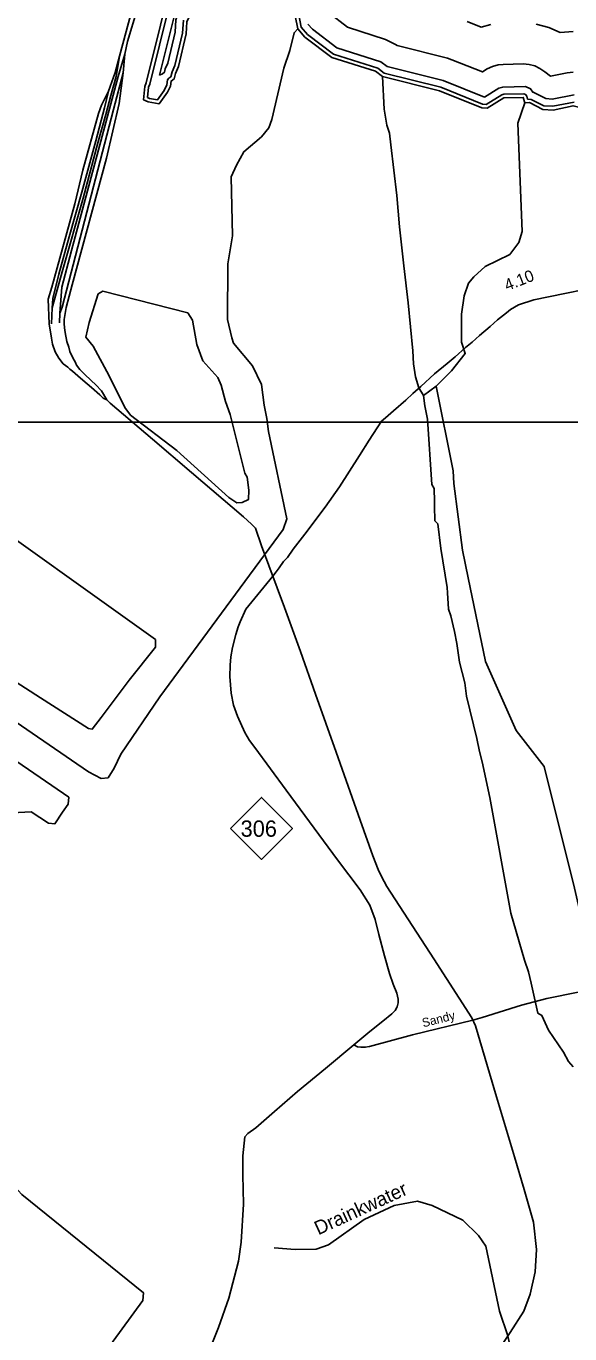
# Model space of a CAD drawing. Extents: x 2532689 to 2764727, y 536648 to 732970.
# Drawn here: x 2661812 to 2667660, y 588019 to 602075 of the extents above; entities that cross this region are included whole.
import ezdxf

# ---------------------------------------------------------------- set-up
doc = ezdxf.new("R2010")
doc.units = 0
for name, color, linetype in [('Exist Hydrographic Buffer Line', 7, 'Continuous'), ('Exist Hydrographic Creek Single Shore', 7, 'Continuous'), ('Exist Hydrographic Creek Single Shore Label', 7, 'Continuous'), ('Exist Hydrographic River Shore', 7, 'Continuous'), ('Exist Railroad Mainline', 7, 'Continuous'), ('Exist Railroad Siding', 7, 'Continuous'), ('Exist Road Primary NC Attributed', 7, 'Continuous'), ('Exist Road Primary NC Mileage Hundredths English Label', 7, 'Continuous'), ('Exist Road Primary NC Shield CELL', 7, 'Continuous'), ('Exist Road Primary NC Shield Number Label', 7, 'Continuous'), ('Exist Road Secondary Type 20 Attributed', 7, 'Continuous'), ('Exist Road Secondary Type 51 Attributed', 7, 'Continuous'), ('Exist Road Secondary Type 51 Label', 7, 'Continuous'), ('Map Preparation Inset Cut Line', 7, 'Continuous')]:
    doc.layers.add(name, color=color, linetype=linetype)

msp = doc.modelspace()

# ---------------------------------------------------------------- linework, layer by layer
at = {"layer": 'Exist Hydrographic Buffer Line'}
for points in [[(2663764, 603955), (2663142, 601452), (2663128, 601418), (2663118, 601309), (2663138, 601299), (2663225, 601283), (2663297, 601385), (2663325, 601443), (2663333, 601498), (2663347, 601516), (2663369, 601532), (2663383, 601584), (2663413, 601654), (2663495, 601999), (2663505, 602138)], [(2663248, 601549), (2663551, 602769), (2663572, 602747), (2663584, 602730), (2663659, 602650), (2663659, 602627), (2663632, 602554), (2663542, 602409), (2663432, 602172), (2663423, 602142), (2663416, 602010), (2663336, 601679), (2663309, 601615), (2663299, 601580), (2663279, 601561), (2663248, 601549)], [(2664745, 602196), (2664771, 602063), (2664838, 601986), (2665118, 601774), (2665594, 601622), (2665663, 601570), (2666273, 601418), (2666722, 601238), (2666761, 601233), (2666930, 601338), (2666950, 601344), (2667166, 601348), (2667185, 601340), (2667197, 601321), (2667206, 601292), (2667245, 601288), (2667381, 601219), (2667476, 601214), (2667705, 601258)], [(2665066, 602222), (2665267, 602063), (2665679, 601933), (2665784, 601879), (2665802, 601866), (2666345, 601730), (2666392, 601715), (2666720, 601584), (2666771, 601616), (2666828, 601642), (2666889, 601658), (2666942, 601664), (2667159, 601669), (2667222, 601664), (2667282, 601647), (2667339, 601621), (2667390, 601585), (2667451, 601536), (2667632, 601574), (2667695, 601579)], [(2664843, 602098), (2664891, 602042), (2665154, 601844), (2665629, 601691), (2665697, 601642), (2666297, 601492), (2666742, 601313), (2666744, 601313), (2666898, 601409), (2666938, 601421), (2667182, 601426), (2667237, 601401), (2667261, 601364), (2667267, 601364), (2667402, 601296), (2667471, 601292), (2667707, 601337)], [(2666812, 602092), (2666706, 602063), (2666556, 602124)], [(2667695, 602019), (2667556, 602007), (2667433, 602061), (2667298, 602097)]]:
    msp.add_lwpolyline(points, dxfattribs=at)
at = {"layer": 'Exist Hydrographic Creek Single Shore'}
for p, q in [((2666085, 598106), (2666223, 598207)), ((2666205, 596917), (2666204, 596967)), ((2666344, 595983), (2666341, 596042))]:
    msp.add_line(p, q, dxfattribs=at)
for points in [[(2663978, 598922), (2663981, 599519), (2664033, 599823), (2664019, 600457), (2664075, 600580), (2664155, 600725), (2664343, 600887), (2664424, 600982), (2664456, 601072), (2664585, 601625), (2664648, 601812), (2664694, 602004), (2664734, 602045)], [(2665973, 598584), (2665921, 599102), (2665875, 599498), (2665828, 599919), (2665799, 600255), (2665735, 600801), (2665720, 600924), (2665691, 601010), (2665662, 601183), (2665646, 601534)], [(2666494, 598967), (2666495, 598978), (2666523, 599175), (2666570, 599312), (2666627, 599380), (2666749, 599490), (2667013, 599622), (2667111, 599748), (2667149, 599867), (2667099, 601031), (2667177, 601251)], [(2663602, 598914), (2663551, 598993), (2662638, 599225), (2662588, 599197), (2662490, 598890)], [(2666413, 597159), (2666405, 597297), (2666223, 598207), (2666389, 598372), (2666535, 598557), (2666496, 598677), (2666494, 598967)], [(2661638, 594641), (2662484, 594058), (2662619, 593988), (2662694, 593997), (2662758, 594098), (2662830, 594249), (2663250, 594867), (2664577, 596664), (2664616, 596780), (2664420, 597718), (2664400, 597858), (2664372, 598002), (2664342, 598224), (2664246, 598423), (2664041, 598668), (2664023, 598726), (2663978, 598922)], [(2664209, 597089), (2664203, 596987), (2664137, 596955), (2664079, 596952), (2663994, 597008), (2663433, 597514), (2662933, 597894), (2662872, 597977), (2662706, 598315), (2662533, 598637), (2662456, 598732), (2662490, 598890)], [(2663602, 598914), (2663649, 598652), (2663712, 598477), (2663874, 598297), (2663909, 598216), (2663955, 598041), (2664008, 597902), (2664163, 597271), (2664189, 597229), (2664209, 597089)], [(2666204, 596967), (2666201, 597107), (2666175, 597149), (2666128, 597850), (2666102, 597993), (2666085, 598106), (2666035, 598187), (2665999, 598304), (2665979, 598444), (2665973, 598584)], [(2662482, 594524), (2661966, 594854), (2660571, 595750), (2660426, 595889), (2660307, 596028), (2660280, 596086), (2660286, 596192), (2660488, 596857), (2660534, 597032), (2660574, 597142), (2660589, 597209), (2660612, 597285), (2660705, 597627), (2660805, 597615), (2660882, 597500), (2660902, 597399), (2660940, 597174), (2661052, 597017), (2663203, 595482), (2663204, 595400), (2662920, 595044), (2662621, 594644), (2662524, 594519), (2662482, 594524)], [(2666565, 596144), (2666507, 596441), (2666413, 597159)], [(2666341, 596042), (2666273, 596460), (2666242, 596725), (2666208, 596759), (2666205, 596917)], [(2669946, 590196), (2669863, 590163), (2669646, 590184), (2669410, 590286), (2668660, 590676), (2668524, 590792), (2668430, 590913), (2668334, 591086), (2668179, 591316), (2668048, 591597), (2668013, 591648), (2667959, 591813), (2667941, 591911), (2667906, 591995), (2667903, 592093), (2667814, 592359), (2667712, 592808), (2667384, 594118), (2667083, 594503), (2666754, 595244), (2666565, 596144)], [(2667697, 590890), (2667645, 590947), (2667593, 591046), (2667429, 591283), (2667359, 591441), (2667317, 591465), (2667243, 591787), (2667216, 591911), (2667171, 592037), (2667027, 592540), (2666799, 593785), (2666716, 594169), (2666688, 594277), (2666660, 594417), (2666550, 594872), (2666530, 595016), (2666475, 595237), (2666446, 595439), (2666418, 595569), (2666381, 595735), (2666354, 595810), (2666344, 595983)], [(2660581, 594943), (2662273, 593786), (2662266, 593711), (2662202, 593626), (2662121, 593501), (2662054, 593508), (2661868, 593629), (2661594, 593615)], [(2662526, 587634), (2663068, 588378), (2663074, 588460), (2661767, 589517), (2661648, 589647), (2661577, 589845), (2661452, 591327), (2661433, 591444), (2661356, 591550), (2661185, 591720), (2661081, 591909), (2661070, 592017)], [(2667096, 587500), (2666994, 587998), (2666904, 588264), (2666756, 588960), (2666678, 589075), (2666508, 589239), (2666179, 589397), (2666020, 589443), (2665771, 589397), (2665449, 589249), (2665063, 588974), (2664931, 588929), (2664706, 588924), (2664481, 588944)]]:
    msp.add_lwpolyline(points, dxfattribs=at)
at = {"layer": 'Exist Hydrographic River Shore'}
for points in [[(2663972, 602963), (2663890, 602927), (2663698, 602916), (2663666, 602888), (2663676, 602807), (2663778, 602699), (2663780, 602607), (2663741, 602501), (2663644, 602346), (2663541, 602122), (2663535, 601993), (2663451, 601642), (2663420, 601568), (2663404, 601509), (2663371, 601484), (2663364, 601431), (2663332, 601365), (2663243, 601240), (2663126, 601261), (2663076, 601285), (2663089, 601427), (2663105, 601467), (2663725, 603964)], [(2664734, 602045), (2664706, 602188), (2664672, 602230), (2664636, 602327), (2664550, 602491), (2664156, 602934), (2664114, 602975), (2663972, 602963)], [(2665646, 601534), (2665570, 601590), (2665100, 601738), (2664811, 601956), (2664734, 602045)], [(2667177, 601251), (2667159, 601309), (2666951, 601304), (2666770, 601192), (2666712, 601199), (2666258, 601381), (2665646, 601534)], [(2670611, 600199), (2670433, 600221), (2669508, 600636), (2668986, 600864), (2668659, 600976), (2667695, 601219), (2667479, 601174), (2667371, 601180), (2667227, 601253), (2667177, 601251)]]:
    msp.add_lwpolyline(points, dxfattribs=at)
at = {"layer": 'Exist Railroad Mainline'}
for points in [[(2665693, 592828), (2665635, 592934), (2665599, 593010), (2665542, 593158), (2665405, 593539), (2665147, 594272), (2664923, 594895), (2664763, 595354), (2664591, 595826), (2664344, 596489), (2664278, 596679), (2664237, 596722), (2664149, 596802), (2663590, 597278), (2663170, 597635), (2662716, 598023), (2662681, 598060)], [(2666770, 587664), (2667020, 588032), (2667167, 588263), (2667235, 588445), (2667287, 588684), (2667300, 588926), (2667268, 589220), (2667168, 589570), (2667064, 589923), (2666871, 590565), (2666722, 591074), (2666645, 591328), (2666605, 591414), (2666199, 592049), (2665693, 592828)]]:
    msp.add_lwpolyline(points, dxfattribs=at)
at = {"layer": 'Exist Railroad Siding'}
for p, q in [((2662948, 602242), (2662817, 601752)), ((2662857, 601572), (2662874, 601773)), ((2662092, 599049), (2662084, 598877)), ((2662174, 598991), (2662170, 598887))]:
    msp.add_line(p, q, dxfattribs=at)
for points in [[(2663435, 603923), (2663055, 602465), (2663006, 602254), (2662901, 601909), (2662874, 601773)], [(2662874, 601773), (2662802, 601535), (2662301, 599663), (2662195, 599271), (2662174, 598991)], [(2662092, 599049), (2662206, 599459), (2662424, 600228), (2662583, 600820), (2662671, 601124), (2662722, 601329), (2662782, 601534), (2662817, 601752)], [(2662817, 601752), (2662770, 601576), (2662697, 601375)], [(2662857, 601572), (2662751, 601180), (2662198, 599053), (2662174, 598991)], [(2662857, 601572), (2662812, 601245), (2662677, 600656), (2662309, 599294), (2662242, 599050), (2662221, 598922), (2662222, 598880), (2662226, 598834), (2662231, 598782), (2662249, 598687), (2662271, 598623), (2662283, 598579), (2662307, 598526), (2662329, 598484), (2662344, 598461), (2662355, 598431), (2662390, 598384), (2662408, 598366), (2662439, 598333), (2662510, 598266), (2662563, 598220), (2662623, 598155), (2662681, 598060)], [(2662697, 601375), (2662624, 601225), (2662590, 601138), (2662422, 600529), (2662336, 600165), (2662089, 599271), (2662048, 599142), (2662059, 598876), (2662084, 598723), (2662097, 598657), (2662125, 598576), (2662165, 598507), (2662212, 598446), (2662259, 598409), (2662284, 598387), (2662312, 598368), (2662396, 598290), (2662467, 598229), (2662514, 598190), (2662606, 598112), (2662641, 598077), (2662681, 598060)], [(2662697, 601375), (2662655, 601198), (2662561, 600843), (2662413, 600292), (2662275, 599809), (2662165, 599408), (2662098, 599149), (2662092, 599049)]]:
    msp.add_lwpolyline(points, dxfattribs=at)
at = {"layer": 'Exist Road Primary NC Attributed'}
for points in [[(2664467, 596163), (2664500, 596210), (2664533, 596251), (2664582, 596320), (2664623, 596365), (2664685, 596452), (2664811, 596613), (2665029, 596904), (2665182, 597123), (2665397, 597460), (2665501, 597626), (2665635, 597829), (2665676, 597866), (2665762, 597940), (2665897, 598055), (2665973, 598126), (2666056, 598202), (2666206, 598339), (2666340, 598450), (2666428, 598521), (2666539, 598621), (2666610, 598679), (2666687, 598749), (2666803, 598848), (2666881, 598917), (2666980, 598993), (2667023, 599028), (2667109, 599079), (2667272, 599135), (2667431, 599166), (2667994, 599279)], [(2665336, 591125), (2665510, 591267), (2665650, 591379), (2665744, 591460), (2665783, 591496), (2665804, 591535), (2665814, 591575), (2665814, 591616), (2665798, 591681), (2665761, 591779), (2665722, 591891), (2665668, 592082), (2665607, 592311), (2665567, 592474), (2665508, 592628), (2665404, 592792), (2665161, 593114), (2664610, 593864), (2664273, 594320), (2664216, 594395), (2664164, 594483), (2664087, 594659), (2664043, 594778), (2664016, 594907), (2664002, 595084), (2664006, 595207), (2664013, 595297), (2664031, 595397), (2664066, 595537), (2664091, 595617), (2664113, 595671), (2664176, 595809), (2664467, 596163)], [(2663678, 587577), (2663883, 588088), (2663994, 588403), (2664096, 588800), (2664124, 589003), (2664149, 589413), (2664142, 589729), (2664142, 589932), (2664164, 590136), (2664195, 590171), (2664284, 590234), (2664485, 590409), (2664731, 590623), (2665033, 590872), (2665336, 591125)]]:
    msp.add_lwpolyline(points, dxfattribs=at)
at = {"layer": 'Exist Road Primary NC Shield CELL'}
msp.add_lwpolyline([(2664010, 593451), (2664343, 593784), (2664676, 593451), (2664343, 593118)], close=True, dxfattribs=at)
at = {"layer": 'Exist Road Secondary Type 20 Attributed'}
msp.add_lwpolyline([(2666615, 591392), (2666717, 591418), (2667140, 591552), (2667414, 591623), (2667751, 591693), (2667855, 591707), (2667964, 591720), (2668018, 591729), (2668688, 591748), (2669404, 591748), (2669935, 591739), (2670442, 591740), (2670719, 591737), (2670871, 591734), (2670915, 591742), (2671398, 591741), (2673087, 591767), (2674377, 591787), (2674723, 591789)], dxfattribs=at)
at = {"layer": 'Exist Road Secondary Type 51 Attributed'}
msp.add_lwpolyline([(2665336, 591125), (2665378, 591104), (2665412, 591099), (2665459, 591100), (2665507, 591108), (2665969, 591234), (2666615, 591392)], dxfattribs=at)
at = {"layer": 'Map Preparation Inset Cut Line'}
msp.add_lwpolyline([(2674379, 597817), (2625636, 597817), (2625636, 554972), (2674379, 554972)], close=True, dxfattribs=at)

# ---------------------------------------------------------------- texts
at = {"layer": 'Exist Hydrographic Creek Single Shore Label'}
msp.add_text('Drainkwater', height=150, rotation=24.6211, dxfattribs=at).set_placement((2664955, 589077))
at = {"layer": 'Exist Road Primary NC Mileage Hundredths English Label'}
msp.add_text('4.10', height=125, rotation=21.2915, dxfattribs=at).set_placement((2666985, 599227))
at = {"layer": 'Exist Road Primary NC Shield Number Label'}
msp.add_text('306', height=175, dxfattribs=at).set_placement((2664119, 593362))
at = {"layer": 'Exist Road Secondary Type 51 Label'}
msp.add_text('Sandy', height=95, rotation=14.1392, dxfattribs=at).set_placement((2666084, 591313))

doc.saveas('drawing.dxf')
